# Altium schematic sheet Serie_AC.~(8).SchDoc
size A4
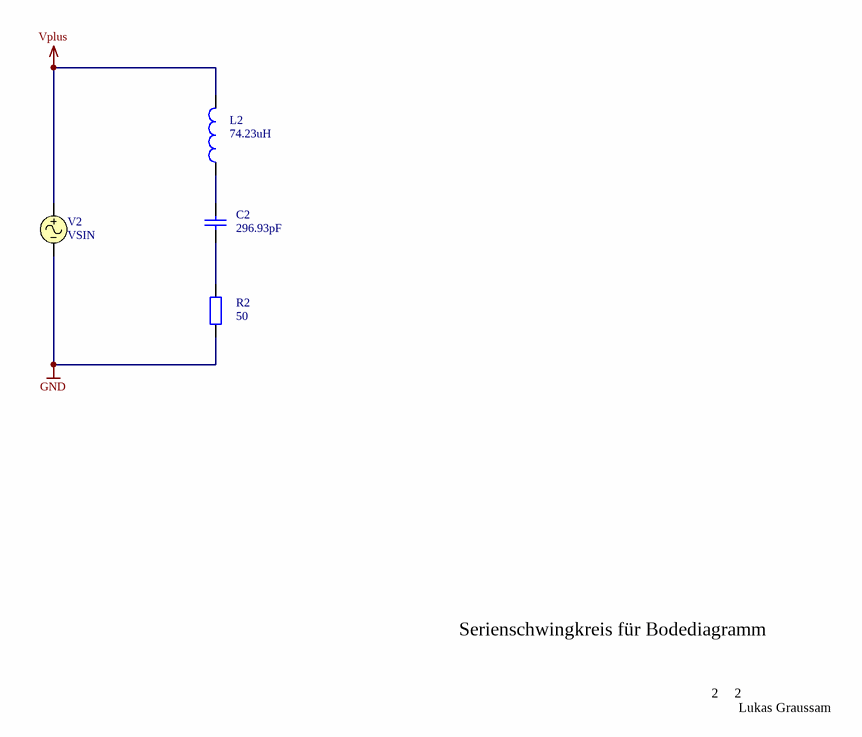
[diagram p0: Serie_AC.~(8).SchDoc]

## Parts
C2  value 296.93pF  [RAD-0.3]  (hidden comment: Cap)
L2  value 74.23uH  [0402-A]  (hidden comment: Inductor)
R2  value 50  [AXIAL-0.4]  (hidden comment: Res2)
V2  VSIN

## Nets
GND: R2.1 V2.2
Vplus: L2.2 V2.1
NetC2_1: C2.1 L2.1
NetC2_2: C2.2 R2.2

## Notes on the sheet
- Serienschwingkreis für Bodediagramm
- 2
- Lukas Graussam

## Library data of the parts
C2 = Cap: Capacitor
L2 = Inductor: Code_IEC: 1005
R2 = Res2: Resistor
V2 = VSIN: Sinusoidal Voltage Source; Note: PCB Footprint - Not required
